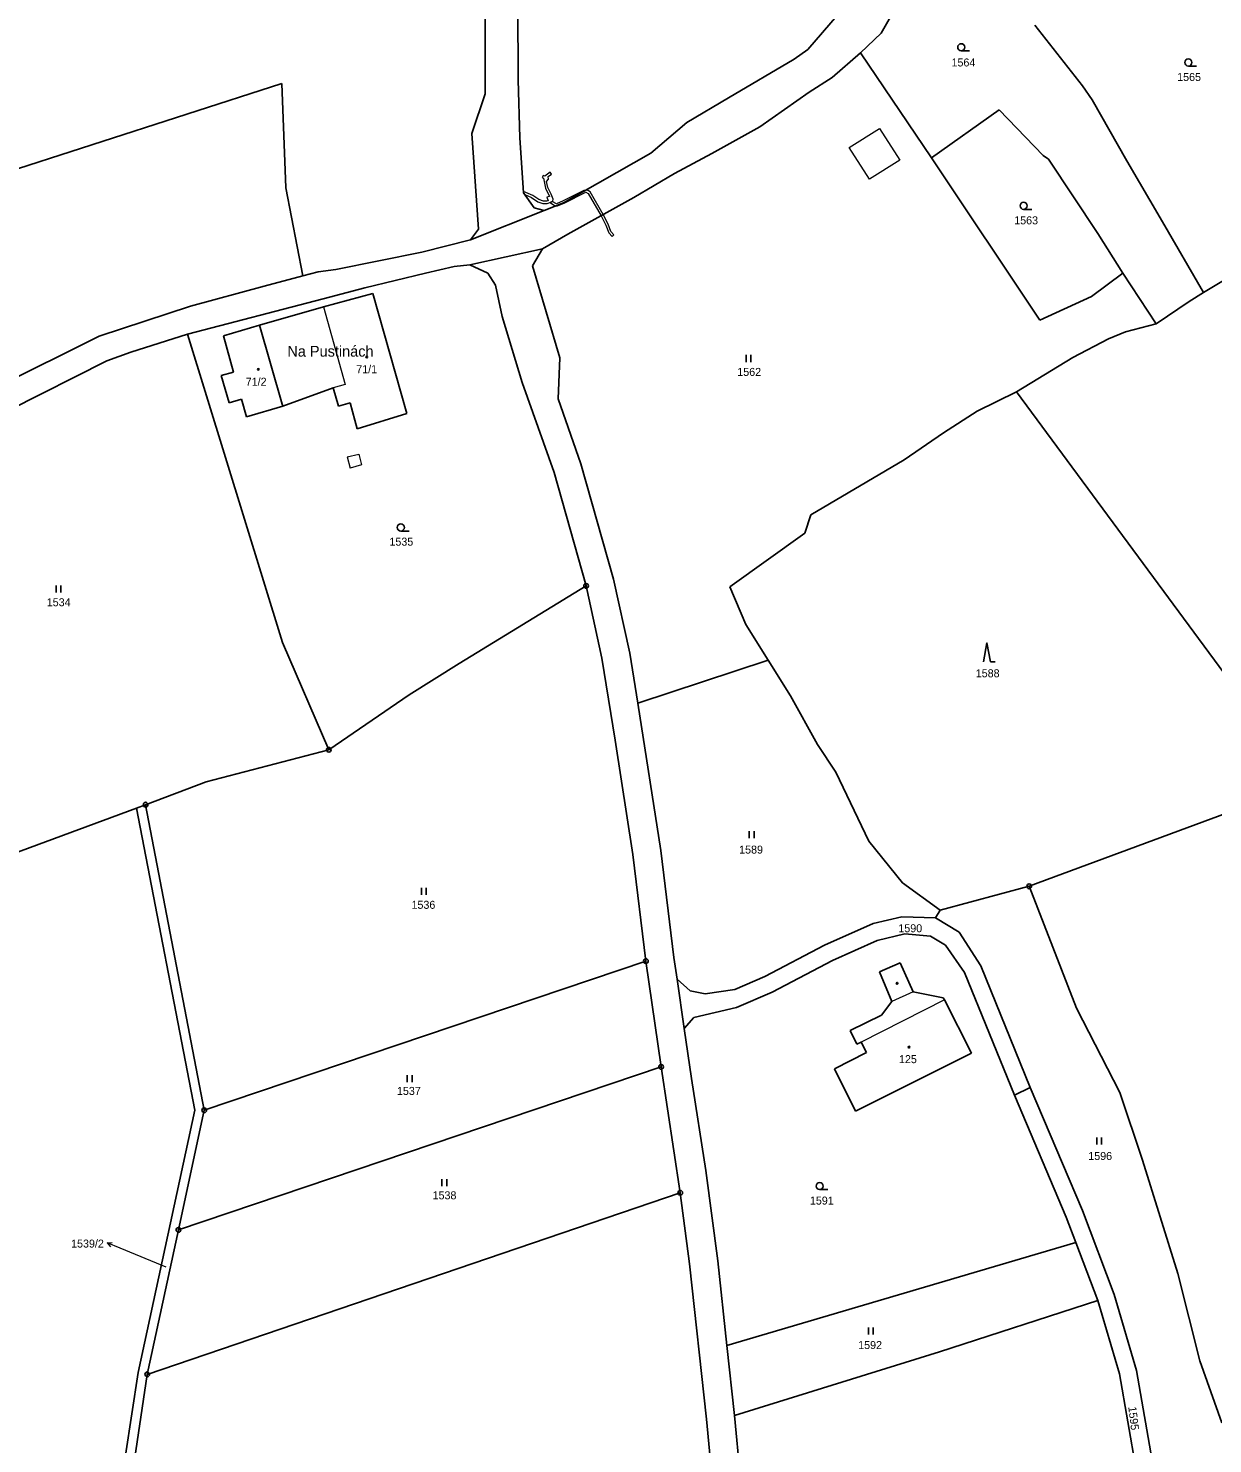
# Model space of a CAD drawing. Extents: x -601131 to -597152, y -1058536 to -1055911.
# Drawn here: x -599835.8 to -599584.4, y -1057934.2 to -1057633.6 of the extents above; entities that cross this region are included whole.
import ezdxf
from ezdxf.enums import TextEntityAlignment as Align

# ---------------------------------------------------------------- set-up
doc = ezdxf.new("R2010")
doc.units = 0
doc.header["$LTSCALE"] = 0.68
for name, color, linetype, lineweight in [('1', 7, 'Continuous', 25), ('13', 7, 'Continuous', 13), ('3', 7, 'Continuous', 25), ('4', 7, 'Continuous', 13), ('5', 7, 'Continuous', 25), ('7', 7, 'Continuous', 13), ('8', 7, 'Continuous', 25)]:
    doc.layers.add(name, color=color, linetype=linetype, lineweight=lineweight)
doc.layers.add('2', color=7, linetype='Continuous')

msp = doc.modelspace()

# ---------------------------------------------------------------- linework, layer by layer
at = {"layer": '1'}
for p, q in [((-599738.87, -1057628.57), (-599738.85, -1057647.48)), ((-599731.85, -1057644.53), (-599731.87, -1057628.73)), ((-599662.35, -1057628.79), (-599670.36, -1057638.06)), ((-599651.06, -1057628.02), (-599654.79, -1057634.62)), ((-599654.79, -1057634.62), (-599659.16, -1057638.81)), ((-599622.14, -1057632.93), (-599612.05, -1057645.83)), ((-599670.36, -1057638.06), (-599673.22, -1057640.17)), ((-599673.22, -1057640.17), (-599687.22, -1057648.36)), ((-599665.16, -1057644.01), (-599659.16, -1057638.81)), ((-599659.16, -1057638.81), (-599644.13, -1057661.11)), ((-599670.07, -1057647.13), (-599665.16, -1057644.01)), ((-599782.01, -1057645.31), (-599878.46, -1057676.47)), ((-599781.16, -1057667.47), (-599782.01, -1057645.31)), ((-599731.46, -1057656.85), (-599731.85, -1057644.53)), ((-599680.55, -1057654.48), (-599670.07, -1057647.13)), ((-599612.05, -1057645.83), (-599609.96, -1057648.79)), ((-599738.85, -1057647.48), (-599741.66, -1057655.93)), ((-599687.22, -1057648.36), (-599696.05, -1057653.59)), ((-599609.96, -1057648.79), (-599602.63, -1057661.74)), ((-599644.13, -1057661.11), (-599629.7, -1057650.92)), ((-599629.7, -1057650.92), (-599620.4, -1057660.63)), ((-599741.66, -1057655.93), (-599740.27, -1057676.27)), ((-599696.05, -1057653.59), (-599703.69, -1057660.14)), ((-599690.74, -1057660.16), (-599680.55, -1057654.48)), ((-599730.7, -1057668.52), (-599731.46, -1057656.85)), ((-599703.69, -1057660.14), (-599722.24, -1057670.67)), ((-599698.63, -1057664.41), (-599690.74, -1057660.16)), ((-599621.1, -1057695.6), (-599644.13, -1057661.11)), ((-599620.4, -1057660.63), (-599619.24, -1057661.38)), ((-599619.24, -1057661.38), (-599608.82, -1057677.19)), ((-599602.63, -1057661.74), (-599595.09, -1057674.72)), ((-599707.26, -1057669.54), (-599698.63, -1057664.41)), ((-599777.55, -1057686.16), (-599781.16, -1057667.47)), ((-599728.47, -1057671.73), (-599730.7, -1057668.52)), ((-599722.24, -1057670.67), (-599726.29, -1057672.28)), ((-599721.32, -1057677.32), (-599707.26, -1057669.54)), ((-599726.29, -1057672.28), (-599741.95, -1057678.48)), ((-599726.29, -1057672.28), (-599728.47, -1057671.73)), ((-599740.27, -1057676.27), (-599741.95, -1057678.48)), ((-599608.82, -1057677.19), (-599603.46, -1057685.58)), ((-599595.09, -1057674.72), (-599586.38, -1057689.73)), ((-599741.95, -1057678.48), (-599752.26, -1057681.15)), ((-599726.67, -1057680.4), (-599721.32, -1057677.32)), ((-599752.26, -1057681.15), (-599770.52, -1057684.83)), ((-599742.1, -1057683.84), (-599726.67, -1057680.4)), ((-599728.77, -1057684.02), (-599726.67, -1057680.4)), ((-599777.55, -1057686.16), (-599785.76, -1057688.32)), ((-599774.26, -1057685.29), (-599777.55, -1057686.16)), ((-599770.52, -1057684.83), (-599774.26, -1057685.29)), ((-599764.37, -1057688.7), (-599751.49, -1057685.6)), ((-599751.49, -1057685.6), (-599745.42, -1057684.21)), ((-599745.42, -1057684.21), (-599742.1, -1057683.84)), ((-599742.1, -1057683.84), (-599738.25, -1057685.61)), ((-599738.25, -1057685.61), (-599736.62, -1057688.14)), ((-599723.01, -1057703.58), (-599728.77, -1057684.02)), ((-599603.46, -1057685.58), (-599610.14, -1057690.54)), ((-599603.46, -1057685.58), (-599596.38, -1057696.38)), ((-599785.76, -1057688.32), (-599801.42, -1057692.59)), ((-599773.24, -1057691.07), (-599764.37, -1057688.7)), ((-599736.62, -1057688.14), (-599735.2, -1057694.8)), ((-599586.38, -1057689.73), (-599582.14, -1057687.14)), ((-599802.02, -1057698.57), (-599773.24, -1057691.07)), ((-599773.18, -1057692.77), (-599762.65, -1057689.91)), ((-599762.65, -1057689.91), (-599755.45, -1057715.39)), ((-599610.14, -1057690.54), (-599621.1, -1057695.6)), ((-599596.38, -1057696.38), (-599589.43, -1057691.59)), ((-599589.43, -1057691.59), (-599586.38, -1057689.73)), ((-599801.42, -1057692.59), (-599820.76, -1057698.99)), ((-599786.74, -1057696.64), (-599773.18, -1057692.77)), ((-599735.2, -1057694.8), (-599730.97, -1057708.8)), ((-599794.4, -1057698.9), (-599786.74, -1057696.64)), ((-599781.96, -1057713.38), (-599786.74, -1057696.64)), ((-599602.95, -1057698.04), (-599606.54, -1057699.53)), ((-599596.38, -1057696.38), (-599602.95, -1057698.04)), ((-599820.76, -1057698.99), (-599842.59, -1057709.8)), ((-599814.08, -1057702.37), (-599802.02, -1057698.57)), ((-599802.02, -1057698.57), (-599781.89, -1057764.04)), ((-599792.25, -1057706.61), (-599794.4, -1057698.9)), ((-599606.54, -1057699.53), (-599614.07, -1057703.49)), ((-599839.9, -1057714.66), (-599819.15, -1057704.19)), ((-599819.15, -1057704.19), (-599814.08, -1057702.37)), ((-599723.37, -1057712.3), (-599723.01, -1057703.58)), ((-599614.07, -1057703.49), (-599626.08, -1057710.77)), ((-599794.85, -1057707.31), (-599792.25, -1057706.61)), ((-599793.17, -1057713.1), (-599794.85, -1057707.31)), ((-599771.07, -1057709.94), (-599781.76, -1057713.87)), ((-599769.98, -1057713.84), (-599771.07, -1057709.94)), ((-599730.97, -1057708.8), (-599724.22, -1057727.9)), ((-599790.58, -1057712.35), (-599793.17, -1057713.1)), ((-599789.52, -1057716.11), (-599790.58, -1057712.35)), ((-599767.51, -1057713.15), (-599769.98, -1057713.84)), ((-599765.99, -1057718.66), (-599767.51, -1057713.15)), ((-599718.51, -1057726.06), (-599723.37, -1057712.3)), ((-599626.08, -1057710.77), (-599634.41, -1057714.91)), ((-599564.68, -1057794.05), (-599626.08, -1057710.77)), ((-599781.76, -1057713.87), (-599789.52, -1057716.11)), ((-599781.76, -1057713.87), (-599781.96, -1057713.38)), ((-599755.45, -1057715.39), (-599765.99, -1057718.66)), ((-599634.41, -1057714.91), (-599641.58, -1057719.49)), ((-599641.58, -1057719.49), (-599649.93, -1057725.21)), ((-599649.93, -1057725.21), (-599669.73, -1057736.95)), ((-599724.22, -1057727.9), (-599717.41, -1057752.01)), ((-599711.58, -1057750.59), (-599718.51, -1057726.06)), ((-599669.73, -1057736.95), (-599670.97, -1057740.82)), ((-599670.97, -1057740.82), (-599686.92, -1057752.18)), ((-599717.41, -1057752.01), (-599744.34, -1057768.46)), ((-599714.07, -1057767.34), (-599717.41, -1057752.01)), ((-599708.16, -1057766.32), (-599711.58, -1057750.59)), ((-599686.92, -1057752.18), (-599683.52, -1057760.21)), ((-599683.52, -1057760.21), (-599678.75, -1057767.79)), ((-599781.89, -1057764.04), (-599772.03, -1057786.82)), ((-599711.24, -1057784.77), (-599714.07, -1057767.34)), ((-599706.44, -1057776.89), (-599708.16, -1057766.32)), ((-599744.34, -1057768.46), (-599754.96, -1057775.14)), ((-599678.75, -1057767.79), (-599706.44, -1057776.89)), ((-599678.75, -1057767.79), (-599674, -1057775.32)), ((-599754.96, -1057775.14), (-599772.03, -1057786.82)), ((-599674, -1057775.32), (-599668.32, -1057785.69)), ((-599701.52, -1057808.21), (-599706.44, -1057776.89)), ((-599707.46, -1057809.03), (-599711.24, -1057784.77)), ((-599772.03, -1057786.82), (-599798.05, -1057793.59)), ((-599668.32, -1057785.69), (-599664.38, -1057791.6)), ((-599798.05, -1057793.59), (-599810.92, -1057798.47)), ((-599664.38, -1057791.6), (-599657.43, -1057806.19)), ((-599564.68, -1057794.05), (-599623.35, -1057815.81)), ((-599812.82, -1057799.18), (-599810.92, -1057798.47)), ((-599810.92, -1057798.47), (-599798.46, -1057863.37)), ((-599657.43, -1057806.19), (-599650.26, -1057815.09)), ((-599704.72, -1057831.68), (-599707.46, -1057809.03)), ((-599698.77, -1057830.94), (-599701.52, -1057808.21)), ((-599650.26, -1057815.09), (-599642.23, -1057820.86)), ((-599642.23, -1057820.86), (-599623.35, -1057815.81)), ((-599623.35, -1057815.81), (-599613.29, -1057841.68)), ((-599643.28, -1057822.49), (-599642.23, -1057820.86)), ((-599666.8, -1057828.29), (-599656.51, -1057823.72)), ((-599656.51, -1057823.72), (-599650.36, -1057822.26)), ((-599650.36, -1057822.26), (-599643.28, -1057822.49)), ((-599638.19, -1057825.56), (-599643.28, -1057822.49)), ((-599655.6, -1057827.31), (-599665.12, -1057831.59)), ((-599649.78, -1057825.92), (-599655.6, -1057827.31)), ((-599644.33, -1057826.42), (-599649.78, -1057825.92)), ((-599641.14, -1057828.34), (-599644.33, -1057826.42)), ((-599633.65, -1057832.69), (-599638.19, -1057825.56)), ((-599679.44, -1057834.96), (-599666.8, -1057828.29)), ((-599637.07, -1057834.11), (-599641.14, -1057828.34)), ((-599798.46, -1057863.37), (-599704.72, -1057831.68)), ((-599704.72, -1057831.68), (-599701.48, -1057854.16)), ((-599698.11, -1057835.5), (-599698.77, -1057830.94)), ((-599665.12, -1057831.59), (-599677.9, -1057838.32)), ((-599655.13, -1057834), (-599650.77, -1057832.07)), ((-599650.77, -1057832.07), (-599648.01, -1057838.19)), ((-599623.17, -1057858.55), (-599633.65, -1057832.69)), ((-599698.11, -1057835.5), (-599695.33, -1057837.97)), ((-599696.59, -1057846.03), (-599698.11, -1057835.5)), ((-599685.81, -1057837.71), (-599679.44, -1057834.96)), ((-599652.5, -1057840.26), (-599655.13, -1057834)), ((-599626.5, -1057860.17), (-599637.07, -1057834.11)), ((-599695.33, -1057837.97), (-599692.13, -1057838.65)), ((-599692.13, -1057838.65), (-599685.81, -1057837.71)), ((-599677.9, -1057838.32), (-599685.49, -1057841.54)), ((-599648.01, -1057838.19), (-599641.59, -1057839.47)), ((-599641.59, -1057839.47), (-599641.33, -1057839.91)), ((-599685.49, -1057841.54), (-599694.51, -1057843.67)), ((-599654.7, -1057843.15), (-599652.5, -1057840.26)), ((-599641.33, -1057839.91), (-599635.61, -1057851.22)), ((-599613.29, -1057841.68), (-599604.12, -1057859.58)), ((-599694.51, -1057843.67), (-599696.59, -1057846.03)), ((-599661.35, -1057846.42), (-599654.7, -1057843.15)), ((-599696.59, -1057846.03), (-599695.07, -1057856.6)), ((-599659.98, -1057849.32), (-599661.35, -1057846.42)), ((-599664.7, -1057854.6), (-599657.92, -1057851.13)), ((-599635.61, -1057851.22), (-599660.23, -1057863.55)), ((-599659.03, -1057848.88), (-599659.98, -1057849.32)), ((-599657.92, -1057851.13), (-599659.03, -1057848.88)), ((-599701.48, -1057854.16), (-599803.95, -1057888.79)), ((-599701.48, -1057854.16), (-599697.43, -1057880.9)), ((-599695.07, -1057856.6), (-599692.01, -1057876.15)), ((-599660.23, -1057863.55), (-599664.7, -1057854.6)), ((-599623.17, -1057858.55), (-599626.5, -1057860.17)), ((-599615.48, -1057886.04), (-599626.5, -1057860.17)), ((-599612.04, -1057884.68), (-599623.17, -1057858.55)), ((-599604.12, -1057859.58), (-599599.32, -1057873.97)), ((-599800.5, -1057863.35), (-599812.53, -1057919.09)), ((-599803.95, -1057888.79), (-599798.46, -1057863.37)), ((-599599.32, -1057873.97), (-599591.8, -1057898.07)), ((-599692.01, -1057876.15), (-599689.47, -1057895.33)), ((-599697.43, -1057880.9), (-599810.56, -1057919.45)), ((-599695.43, -1057895.99), (-599697.43, -1057880.9)), ((-599613.44, -1057891.47), (-599615.48, -1057886.04)), ((-599605.31, -1057902.53), (-599612.04, -1057884.68)), ((-599810.56, -1057919.45), (-599803.95, -1057888.79)), ((-599687.51, -1057913.3), (-599613.44, -1057891.47)), ((-599613.44, -1057891.47), (-599608.79, -1057903.8)), ((-599691.84, -1057928.97), (-599695.43, -1057895.99)), ((-599689.47, -1057895.33), (-599687.51, -1057913.3)), ((-599591.8, -1057898.07), (-599587.13, -1057916.58)), ((-599600.58, -1057918.66), (-599605.31, -1057902.53)), ((-599608.79, -1057903.8), (-599642.4, -1057914.65)), ((-599608.79, -1057903.8), (-599604.21, -1057919.37)), ((-599685.89, -1057928.19), (-599687.51, -1057913.3)), ((-599642.4, -1057914.65), (-599685.89, -1057928.19)), ((-599587.13, -1057916.58), (-599582.46, -1057929.77)), ((-599814.31, -1057944.27), (-599810.56, -1057919.45)), ((-599604.21, -1057919.37), (-599600.68, -1057939.71)), ((-599597, -1057939.37), (-599600.58, -1057918.66)), ((-599689.2, -1057956.96), (-599691.84, -1057928.97)), ((-599683.21, -1057956.64), (-599685.89, -1057928.19))]:
    msp.add_line(p, q, dxfattribs=at)
for points in [[(-599844.46, -1057810.92), (-599812.82, -1057799.18), (-599800.5, -1057863.35)], [(-599812.53, -1057919.09), (-599816.5, -1057945.4), (-599814.31, -1057944.27)]]:
    msp.add_lwpolyline(points, dxfattribs=at)
at = {"layer": '13'}
for points in [[(-599727.64, -1057670.42), (-599726.59, -1057670.77), (-599725.67, -1057670.82), (-599724.88, -1057670.53), (-599724.5, -1057670.29), (-599724.4, -1057669.86), (-599724.82, -1057668.82), (-599725.57, -1057667.37), (-599725.8, -1057666.1), (-599725.41, -1057665.6), (-599725.46, -1057665.09), (-599724.74, -1057664.54), (-599725.04, -1057664.14), (-599726.17, -1057665), (-599726.53, -1057664.83), (-599726.74, -1057665.28), (-599726.43, -1057665.43), (-599726.05, -1057667.53), (-599725.15, -1057669.28), (-599725.72, -1057669.48), (-599725.45, -1057670.21), (-599725.75, -1057670.32), (-599726.49, -1057670.27), (-599727.42, -1057669.96), (-599728.73, -1057669.1), (-599730.72, -1057668.22), (-599730.7, -1057668.52), (-599730.44, -1057668.89), (-599728.97, -1057669.54)], [(-599723.73, -1057670.87), (-599724.61, -1057670.36), (-599725.06, -1057670.6), (-599723.93, -1057671.34), (-599722.24, -1057670.67), (-599717.29, -1057667.86), (-599717.86, -1057668), (-599722.28, -1057670.23)], [(-599717.29, -1057667.86), (-599722.24, -1057670.67), (-599723.93, -1057671.34), (-599723.51, -1057671.32), (-599722.06, -1057670.69), (-599717.45, -1057668.36), (-599716.95, -1057668.7), (-599714.22, -1057673.39), (-599713.78, -1057673.15), (-599716.57, -1057668.34)], [(-599711.5, -1057677.47), (-599712.18, -1057676.77), (-599712.75, -1057675.21), (-599713.78, -1057673.15), (-599714.22, -1057673.39), (-599713.21, -1057675.41), (-599712.62, -1057677.05), (-599711.85, -1057677.82)]]:
    msp.add_lwpolyline(points, close=True, dxfattribs=at)
at = {"layer": '3'}
for p, q in [((-599637.783, -1057638.36), (-599636.033, -1057638.36)), ((-599589.573, -1057641.6), (-599587.823, -1057641.6)), ((-599624.543, -1057672.04), (-599622.793, -1057672.04)), ((-599683.441, -1057704.47), (-599683.441, -1057702.97)), ((-599682.44, -1057704.47), (-599682.44, -1057702.97)), ((-599756.743, -1057740.35), (-599754.993, -1057740.35)), ((-599829.911, -1057753.44), (-599829.911, -1057751.94)), ((-599828.91, -1057753.44), (-599828.91, -1057751.94)), ((-599631.59, -1057768.13), (-599630.594, -1057768.13)), ((-599682.771, -1057805.58), (-599682.771, -1057804.08)), ((-599681.77, -1057805.58), (-599681.77, -1057804.08)), ((-599752.371, -1057817.62), (-599752.371, -1057816.12)), ((-599751.37, -1057817.62), (-599751.37, -1057816.12)), ((-599755.361, -1057857.4), (-599755.361, -1057855.9)), ((-599754.36, -1057857.4), (-599754.36, -1057855.9)), ((-599609.031, -1057870.65), (-599609.031, -1057869.15)), ((-599608.03, -1057870.65), (-599608.03, -1057869.15)), ((-599748.011, -1057879.49), (-599748.011, -1057877.99)), ((-599747.01, -1057879.49), (-599747.01, -1057877.99)), ((-599667.833, -1057880.22), (-599666.083, -1057880.22)), ((-599657.491, -1057911), (-599657.491, -1057909.5)), ((-599656.49, -1057911), (-599656.49, -1057909.5))]:
    msp.add_line(p, q, dxfattribs=at)
msp.add_lwpolyline([(-599631.59, -1057768.13), (-599632.34, -1057764.13), (-599633.09, -1057768.13)], dxfattribs=at)
for centre in [(-599637.7829, -1057637.6098), (-599589.5729, -1057640.8498), (-599624.5429, -1057671.2898), (-599756.7429, -1057739.5998), (-599667.8329, -1057879.4698)]:
    msp.add_circle(centre, 0.75, dxfattribs=at)
at = {"layer": '4'}
for p, q in [((-599661.57, -1057658.89), (-599655.14, -1057654.86)), ((-599655.14, -1057654.86), (-599650.83, -1057661.59)), ((-599657.29, -1057665.63), (-599661.57, -1057658.89)), ((-599650.83, -1057661.59), (-599657.29, -1057665.63)), ((-599773.18, -1057692.77), (-599768.57, -1057709.24)), ((-599768.57, -1057709.24), (-599771.07, -1057709.94)), ((-599768.11, -1057724.63), (-599765.62, -1057724.02)), ((-599768.11, -1057724.63), (-599767.51, -1057726.98)), ((-599765.62, -1057724.02), (-599765.06, -1057726.31)), ((-599765.06, -1057726.31), (-599767.51, -1057726.98)), ((-599648.01, -1057838.19), (-599652.5, -1057840.26)), ((-599641.33, -1057839.91), (-599659.03, -1057848.88))]:
    msp.add_line(p, q, dxfattribs=at)
at = {"layer": '5'}
for centre in [(-599763.9668, -1057703.3792), (-599786.9968, -1057706.0292), (-599651.3968, -1057836.4092), (-599648.8868, -1057849.9592)]:
    msp.add_circle(centre, 0.175, dxfattribs=at)
at = {"layer": '7'}
msp.add_line((-599819.102, -1057891.556), (-599818.362, -1057892.395), dxfattribs=at)
msp.add_lwpolyline([(-599806.58, -1057896.7), (-599816.32, -1057892.68), (-599819.102, -1057891.556), (-599817.986, -1057891.467)], dxfattribs=at)
at = {"layer": '8'}
for centre, radius in [((-599717.41, -1057752.0099), 0.5), ((-599717.41, -1057752.0099), 0.0303), ((-599772.03, -1057786.8199), 0.5), ((-599772.03, -1057786.8199), 0.0303), ((-599810.92, -1057798.4699), 0.5), ((-599810.92, -1057798.4699), 0.0303), ((-599623.35, -1057815.8099), 0.5), ((-599623.35, -1057815.8099), 0.0303), ((-599704.72, -1057831.6799), 0.5), ((-599704.72, -1057831.6799), 0.0303), ((-599701.48, -1057854.1599), 0.5), ((-599701.48, -1057854.1599), 0.0303), ((-599798.46, -1057863.3699), 0.5), ((-599798.46, -1057863.3699), 0.0303), ((-599697.43, -1057880.8999), 0.5), ((-599697.43, -1057880.8999), 0.0303), ((-599803.95, -1057888.7899), 0.5), ((-599803.95, -1057888.7899), 0.0303), ((-599810.56, -1057919.4499), 0.5), ((-599810.56, -1057919.4499), 0.0303)]:
    msp.add_circle(centre, radius, dxfattribs=at)

# ---------------------------------------------------------------- texts
at = {"layer": '2'}
for s, p in [('1564', (-599637.32, -1057641.692)), ('1565', (-599589.42, -1057644.782)), ('1563', (-599624.01, -1057675.222)), ('71/1', (-599763.989, -1057706.832)), ('1562', (-599682.79, -1057707.412)), ('71/2', (-599787.449, -1057709.492)), ('1535', (-599756.63, -1057743.462)), ('1534', (-599829.37, -1057756.332)), ('1588', (-599632.17, -1057771.412)), ('1589', (-599682.4, -1057808.862)), ('1536', (-599751.95, -1057820.582)), ('1590', (-599648.6, -1057825.562)), ('125', (-599649.099, -1057853.362)), ('1537', (-599755.03, -1057860.112)), ('1596', (-599608.29, -1057873.932)), ('1538', (-599747.47, -1057882.282)), ('1591', (-599667.38, -1057883.402)), ('1592', (-599657.13, -1057914.082))]:
    msp.add_text(s, height=1.7, dxfattribs=at).set_placement(p, align=Align.CENTER)
msp.add_text('1539/2', height=1.7, dxfattribs=at).set_placement((-599819.779, -1057892.532), align=Align.RIGHT)
msp.add_text('1595', height=1.7, rotation=277, dxfattribs=at).set_placement((-599602.0262, -1057928.8884), align=Align.CENTER)
at = {"layer": '7'}
msp.add_text('Na Pustinách', height=2.3, dxfattribs=at).set_placement((-599771.68, -1057703.325), align=Align.CENTER)

doc.saveas('drawing.dxf')
